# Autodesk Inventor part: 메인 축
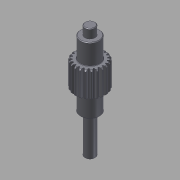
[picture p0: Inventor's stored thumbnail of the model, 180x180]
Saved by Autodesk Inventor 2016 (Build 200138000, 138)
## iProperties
Created: 2016-02
Part Number: 메인 축
Material: 강철, 연강
Document SubType Name: Modeling
Categories: <?xml version="1.0" encoding="UTF-16"?> <MemberInstance><Categories><FamilyTemplate><FamilyTemplateParameter ValueType="xs:double" Id="1" ObjectReferenceKey="da
Density: 7.86 g/cm^3
Appearance: 강철
CustomPartVersion: 1
Author: mdu
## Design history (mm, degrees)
sketch "Sketch1"
  geometry: C1 r 12 at (0, 0)
  constraints: 1 centre point
  dimensions: "d0" = 24 diameter of C1 (= da_da)
extrude "Extrusion1" new body sketch "Sketch1" distance "d1" = 20 (= da_b); taper "d2" = 0 deg
workplane "Work Plane2"
feature "피치 지름" dims "d4" = 10, "d5" = 0
workplane "Work Plane8"
workplane "Work Plane9"
chamfer "모따기1" distance "d49" = 1; stored, may be unused: second distance "d50" = 2, angle "d51" = 45 deg
sketch "스케치3"
  geometry: C1 r 7.5 at (0, 0); 1 further point
  constraints: 1 centre point, 1 coincident
  dimensions: "d52" = 15 diameter of C1
extrude "돌출2" join sketch "스케치3" distance "d53" = 16; taper "d54" = 0 deg
sketch "스케치4"
  geometry: C1 r 4 at (0, 0); 1 further point
  constraints: 1 centre point, 1 coincident
  dimensions: "d55" = 8 diameter of C1
extrude "돌출3" join sketch "스케치4" distance "d56" = 7; taper "d57" = 0 deg
sketch "스케치5"
  geometry: C1 r 7.5 at (0, 0) reference; C2 r 7.5 at (0, 0) reference; 1 further point
extrude "돌출4" join sketch "스케치5" distance "d62" = 16; taper "d63" = 0 deg
sketch "스케치6"
  geometry: C1 r 4 at (0, 0); 1 further point
  constraints: 1 centre point, 1 coincident
  dimensions: "d64" = 8 diameter of C1
extrude "돌출5" join sketch "스케치6" distance "d65" = 30; taper "d66" = 0 deg
chamfer "모따기2" distance "d58" = 0.5; stored, may be unused: second distance "d59" = 2, angle "d60" = 45 deg
fillet "모깎기1" dims "d61" = 0.3
feature "스퍼 기어" dims "d34" = 1.428 (computed from da_z), "da_b" = 20, "da_d" = 22, "da_aw" = 31, "da_da" = 24, "da_df" = 19.5, "da_dw" = 22, angle "da_beta" = 0 deg, "da_lefttooth" = 0, "da_righttooth" = 0
body "Solid1"
sketch "Sketch2"
  geometry: C1 r 12 at (0, 0) reference; C2 r 11 at (0, 0)
  constraints: 1 centre point, 1 coincident
  dimensions: "d3" = 22 diameter of C2 (= da_dw)
body "Srf1"
node "투영된 루프1"
other parameters: "d16" = 31 (= da_aw), "d17" = 0, "d39" = 0, "d41" = 0, "d43" = 31 (= da_aw), "d46" = 31 (= da_aw), "d47" = 0, "d48" = 0
